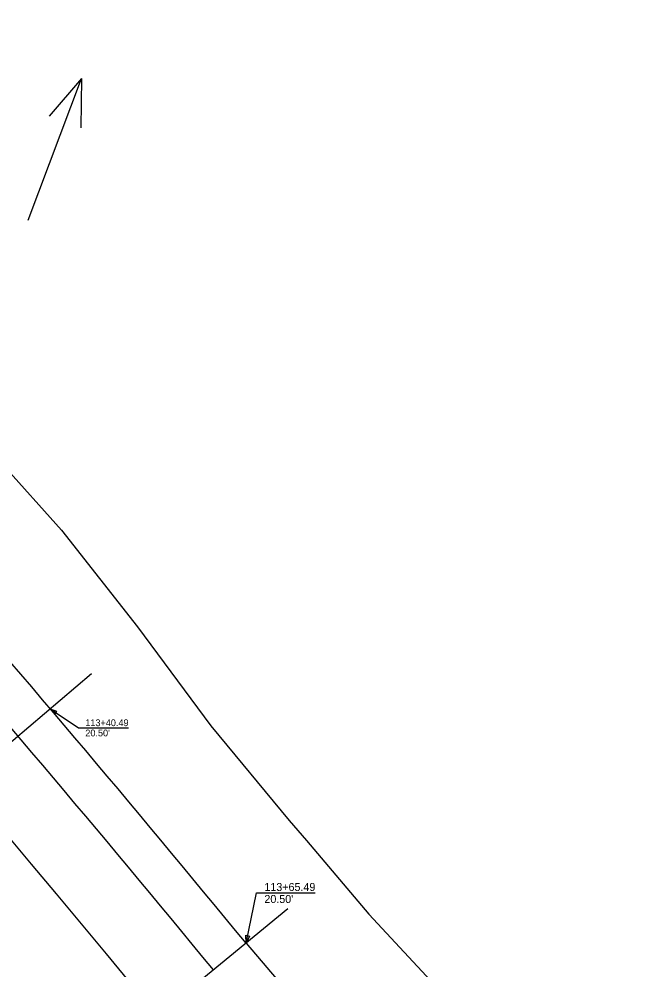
# Model space of a CAD drawing. Extents: x 1006695 to 1009377, y 1883329 to 1886115.
# Drawn here: x 1008005.8 to 1008057.5, y 1884600.5 to 1884679.4 of the extents above; entities that cross this region are included whole.
import ezdxf

# ---------------------------------------------------------------- set-up
doc = ezdxf.new("R2010")
doc.units = 0
for name, color, linetype in [('R_No Plot', 7, 'Continuous'), ('R_Prop Const Limits Cut', 7, 'Continuous'), ('R_Prop EOL', 7, 'Continuous'), ('R_Prop EOS', 7, 'Continuous'), ('R_Prop Guardrail', 7, 'Continuous'), ('R_Water Annot', 7, 'Continuous')]:
    doc.layers.add(name, color=color, linetype=linetype)

msp = doc.modelspace()

# ---------------------------------------------------------------- linework, layer by layer
at = {"layer": 'R_No Plot'}
for p, q in [((1008011.771, 1884625.081), (1007992.719, 1884608.895)), ((1008011.252, 1884620.583), (1008014.846, 1884620.583)), ((1008026.113, 1884606.873), (1008030.325, 1884606.873)), ((1008028.07, 1884605.553), (1008008.738, 1884589.702))]:
    msp.add_line(p, q, dxfattribs=at)
for points in [[(1008008.342, 1884622.168), (1008010.688, 1884620.583), (1008011.252, 1884620.583)], [(1008024.59, 1884602.7), (1008025.449, 1884606.873), (1008026.113, 1884606.873)]]:
    msp.add_lwpolyline(points, dxfattribs=at)
for points in [[(1008008.342, 1884622.168), (1008008.872, 1884621.975), (1008008.719, 1884621.748)], [(1008024.59, 1884602.7), (1008024.562, 1884603.364), (1008024.878, 1884603.299)]]:
    msp.add_lwpolyline(points, close=True, dxfattribs=at)
at = {"layer": 'R_Prop Const Limits Cut'}
for points in [[(1008004.311, 1884642.536), (1008009.262, 1884637.01), (1008015.575, 1884628.969), (1008021.658, 1884620.743), (1008028.169, 1884612.881)], [(1008028.169, 1884612.881), (1008029.601, 1884611.218), (1008034.781, 1884605.102), (1008041.75, 1884597.606), (1008048.928, 1884590.262), (1008055.399, 1884582.346), (1008066.945, 1884567.163)]]:
    msp.add_lwpolyline(points, dxfattribs=at)
at = {"layer": 'R_Prop EOL'}
for radius, start in [(1443.394, 37.045062), (1421.394, 35.651642)]:
    msp.add_arc((1006901.082, 1883681.489), radius, start, 53.471968, dxfattribs=at)
at = {"layer": 'R_Prop EOS'}
msp.add_line((1008024.59, 1884602.701), (1008057.646, 1884564.142), dxfattribs=at)
msp.add_arc((1006901.082, 1883681.489), 1452.894, 39.349748, 41.099748, dxfattribs=at)
at = {"layer": 'R_Prop Guardrail'}
msp.add_arc((1006901.082, 1883681.489), 1449.394, 39.349748, 41.099748, dxfattribs=at)
at = {"layer": 'R_Water Annot'}
for p, q in [((1008006.523, 1884662.723), (1008010.922, 1884674.496)), ((1008010.922, 1884674.496), (1008008.264, 1884671.383)), ((1008010.922, 1884674.496), (1008010.887, 1884670.403))]:
    msp.add_line(p, q, dxfattribs=at)

# ---------------------------------------------------------------- texts
at = {"layer": 'R_No Plot'}
for s, height, p in [('113+40.49', 0.5643, (1008011.252, 1884620.724)), ("20.50'", 0.5643, (1008011.252, 1884619.878)), ('113+65.49', 0.6646, (1008026.113, 1884607.04)), ("20.50'", 0.6646, (1008026.113, 1884606.043))]:
    msp.add_text(s, height=height, rotation=360, dxfattribs=at).set_placement(p)

doc.saveas('drawing.dxf')
